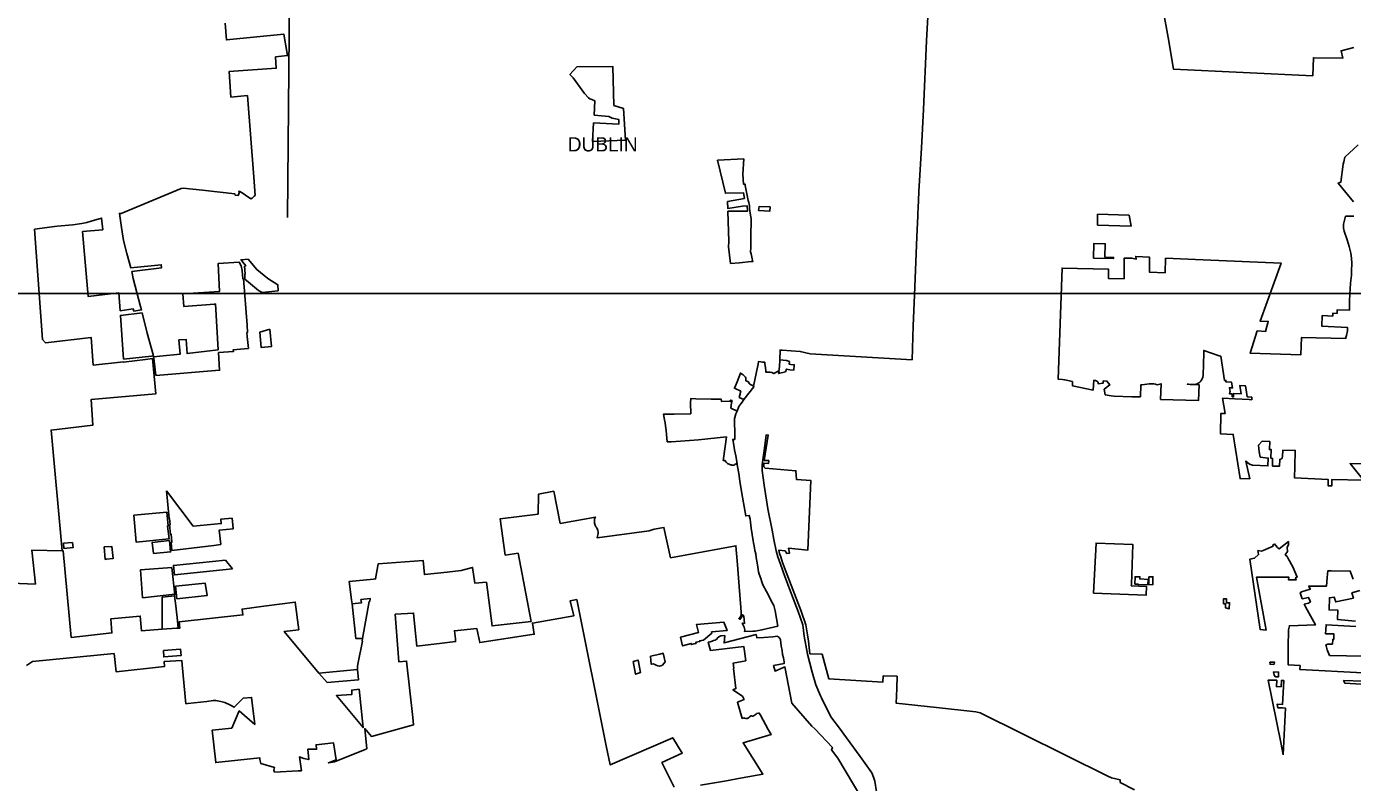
# Model space of a CAD drawing. Extents: x 1729596 to 1925846, y 659247 to 911751.
# Drawn here: x 1771869 to 1818365, y 748344 to 774852 of the extents above; entities that cross this region are included whole.
import ezdxf

# ---------------------------------------------------------------- set-up
doc = ezdxf.new("R2010")
doc.units = 0
for name, color, linetype in [('GM_X_Adjacent_County', 7, 'Continuous'), ('GM_X_Corporation', 7, 'Continuous'), ('GM_X_Corporation_Text', 7, 'Continuous'), ('SC_Scratch1', 7, 'Continuous')]:
    doc.layers.add(name, color=color, linetype=linetype)

msp = doc.modelspace()

# ---------------------------------------------------------------- linework, layer by layer
at = {"layer": 'GM_X_Adjacent_County'}
msp.add_line((1781136, 781321), (1781021, 768152), dxfattribs=at)
at = {"layer": 'GM_X_Corporation'}
for points in [[(1770221, 755380), (1772181, 755302), (1772057, 756492), (1773124, 756470), (1773153, 756469), (1773437, 753432), (1774866, 753591), (1774825, 754079), (1775856, 754180), (1775906, 753660), (1776624, 753722), (1777130, 753751), (1777182, 753756), (1777187, 753756), (1777192, 753756), (1777203, 753757), (1777227, 753759), (1777248, 753761), (1777222, 753980), (1779459, 754220), (1779429, 754427), (1780187, 754529), (1781295, 754669), (1781415, 753697), (1780909, 753642), (1782119, 752179), (1782408, 751849), (1783508, 751942), (1783479, 752309), (1783471, 752408), (1783484, 752497), (1783649, 753302), (1783633, 753301), (1783649, 753390), (1783882, 754688), (1783903, 754693), (1783921, 754795), (1783593, 754757), (1783615, 754639), (1783284, 754607), (1783265, 754751), (1783184, 755392), (1784040, 755478), (1784107, 755485), (1784200, 756011), (1785774, 756133), (1785821, 755634), (1786620, 755722), (1787106, 755772), (1787508, 755887), (1787585, 755334), (1787998, 755364), (1788193, 753835), (1789563, 753993), (1789108, 756382), (1788659, 756318), (1788479, 757590), (1789807, 757755), (1789818, 758450), (1790355, 758555), (1790586, 757428), (1791817, 757651), (1791798, 757614), (1791788, 757587), (1791780, 757546), (1791782, 757487), (1791788, 757438), (1791805, 757364), (1791835, 757312), (1791867, 757269), (1791892, 757218), (1791908, 757179), (1791915, 757135), (1791911, 757075), (1791904, 757024), (1791892, 756983), (1791876, 756928), (1793703, 757167), (1793873, 757222), (1794220, 757291), (1794455, 756226), (1796742, 756644), (1796798, 755979), (1796859, 755222), (1796915, 754482), (1796927, 754304), (1796931, 754250), (1796929, 754213), (1796912, 754181), (1796877, 754133), (1796843, 754097), (1796883, 754064), (1796952, 754150), (1796983, 754223), (1797022, 754175), (1797047, 753919), (1796968, 753934), (1797035, 753796), (1797053, 753693), (1797049, 753638), (1797341, 753647), (1797421, 753653), (1797474, 753661), (1797655, 753696), (1798210, 753829), (1798116, 754362), (1798071, 754553), (1798026, 754636), (1797814, 755043), (1797693, 755276), (1797657, 755384), (1797616, 755493), (1797564, 755654), (1797534, 755727), (1797500, 755975), (1797475, 756104), (1797452, 756237), (1797445, 756358), (1797413, 756483), (1797382, 756639), (1797361, 756753), (1797349, 756823), (1797285, 757257), (1797242, 757581), (1797210, 757710), (1797087, 757691), (1796955, 758481), (1796885, 758915), (1796847, 759179), (1796806, 759422), (1796792, 759498), (1796775, 759605), (1796742, 759796), (1796699, 760004), (1796671, 760173), (1796631, 760376), (1796701, 760373), (1796705, 760456), (1796703, 760557), (1796705, 760694), (1796699, 760891), (1796690, 761106), (1796705, 761148), (1796741, 761269), (1796792, 761362), (1796847, 761530), (1796917, 761623), (1796961, 761681), (1797003, 761733), (1797028, 761773), (1797374, 762223), (1797363, 762240), (1797453, 762684), (1797500, 762912), (1797522, 763017), (1797533, 763101), (1797623, 763091), (1797676, 763083), (1797721, 763081), (1797757, 763077), (1797761, 763030), (1797770, 762968), (1797782, 762885), (1797788, 762787), (1797797, 762730), (1797881, 762730), (1797948, 762730), (1798010, 762716), (1798071, 762682), (1798232, 762768), (1798251, 762763), (1798259, 762760), (1798240, 762681), (1798478, 762748), (1798523, 762842), (1798636, 762814), (1798776, 762808), (1798789, 762992), (1798672, 762998), (1798612, 763008), (1798618, 763105), (1798514, 763138), (1798285, 763163), (1798291, 763505), (1798362, 763501), (1799001, 763458), (1799354, 763375), (1802922, 763165), (1802964, 764353), (1803002, 765433), (1803091, 767476), (1803123, 768218), (1803140, 768585), (1803149, 768674), (1803153, 768757), (1803163, 769065), (1803249, 770602), (1803319, 771942), (1803430, 774349), (1803483, 775420)], [(1803483, 775420), (1803430, 774349), (1803319, 771942), (1803249, 770602), (1803163, 769065), (1803153, 768757), (1803149, 768674), (1803140, 768585), (1803123, 768218), (1803091, 767476), (1803002, 765433), (1802964, 764353), (1802922, 763165), (1799354, 763375), (1799001, 763458), (1798362, 763501), (1798291, 763505), (1798285, 763163), (1798285, 763121), (1798261, 762817), (1798251, 762763), (1798232, 762768), (1798071, 762682), (1798010, 762716), (1797948, 762730), (1797881, 762730), (1797797, 762730), (1797788, 762787), (1797782, 762885), (1797770, 762968), (1797761, 763030), (1797757, 763077), (1797721, 763081), (1797676, 763083), (1797623, 763091), (1797533, 763101), (1797522, 763017), (1797500, 762912), (1797453, 762684), (1797363, 762240), (1797328, 762261), (1797285, 762286), (1797235, 762306), (1797215, 762337), (1797189, 762393), (1797166, 762407), (1797095, 762431), (1797095, 762464), (1797096, 762492), (1797098, 762526), (1797079, 762553), (1797035, 762603), (1796999, 762638), (1796960, 762661), (1796901, 762700), (1796787, 762397), (1796734, 762256), (1796695, 762167), (1796714, 762158), (1796917, 762062), (1796864, 761847), (1797028, 761773), (1797003, 761733), (1796961, 761681), (1796917, 761623), (1796847, 761530), (1796792, 761362), (1796570, 761475), (1796586, 761667), (1796609, 761738), (1796566, 761754), (1796559, 761715), (1796509, 761719), (1796236, 761708), (1796228, 761782), (1795879, 761782), (1795343, 761802), (1795167, 761813), (1795148, 761662), (1795159, 761273), (1794583, 761261), (1794207, 761261), (1794244, 761065), (1794262, 760959), (1794275, 760853), (1794298, 760683), (1794310, 760545), (1794319, 760417), (1794336, 760293), (1794473, 760293), (1794798, 760307), (1795429, 760358), (1796412, 760460), (1796307, 759710), (1796302, 759633), (1796357, 759638), (1796408, 759574), (1796455, 759524), (1796534, 759493), (1796552, 759487), (1796578, 759477), (1796599, 759476), (1796640, 759471), (1796685, 759467), (1796706, 759495), (1796737, 759516), (1796763, 759510), (1796792, 759498), (1796806, 759422), (1796847, 759179), (1796885, 758915), (1796955, 758481), (1797087, 757691), (1797210, 757710), (1797242, 757581), (1797285, 757257), (1797349, 756823), (1797361, 756753), (1797382, 756639), (1797413, 756483), (1797445, 756358), (1797452, 756237), (1797475, 756104), (1797500, 755975), (1797534, 755727), (1797564, 755654), (1797616, 755493), (1797657, 755384), (1797693, 755276), (1797814, 755043), (1798026, 754636), (1798071, 754553), (1798116, 754362), (1798210, 753829), (1797655, 753696), (1797474, 753661), (1797421, 753653), (1797341, 753647), (1797049, 753638), (1797053, 753693), (1797035, 753796), (1796968, 753934), (1797047, 753919), (1797022, 754175), (1796983, 754223), (1796952, 754150), (1796883, 754064), (1796843, 754097), (1796877, 754133), (1796912, 754181), (1796929, 754213), (1796931, 754250), (1796927, 754304), (1796915, 754482), (1796859, 755222), (1796798, 755979), (1796742, 756644), (1794455, 756226), (1794220, 757291), (1793873, 757222), (1793703, 757167), (1791876, 756928), (1791892, 756983), (1791904, 757024), (1791911, 757075), (1791915, 757135), (1791908, 757179), (1791892, 757218), (1791867, 757269), (1791835, 757312), (1791805, 757364), (1791788, 757438), (1791782, 757487), (1791780, 757546), (1791788, 757587), (1791798, 757614), (1791817, 757651), (1790586, 757428), (1790355, 758555), (1789818, 758450), (1789807, 757755), (1788479, 757590), (1788659, 756318), (1789108, 756382), (1789563, 753993), (1788193, 753835), (1787998, 755364), (1787585, 755334), (1787508, 755887), (1787106, 755772), (1786620, 755722), (1785821, 755634), (1785774, 756133), (1784200, 756011), (1784107, 755485), (1784040, 755478), (1783184, 755392), (1783265, 754751), (1783284, 754607), (1783421, 753391), (1783649, 753390), (1783633, 753301), (1783649, 753302), (1783484, 752497), (1783471, 752408), (1783479, 752309), (1782119, 752179), (1780909, 753642), (1781415, 753697), (1781295, 754669), (1780187, 754529), (1779429, 754427), (1779459, 754220), (1777222, 753980), (1777248, 753761), (1777227, 753759), (1777203, 753757), (1777192, 753756), (1777150, 754125), (1777091, 754630), (1777072, 754794), (1777061, 754886), (1776626, 754848), (1776624, 753722), (1775906, 753660), (1775856, 754180), (1774825, 754079), (1774866, 753591), (1773437, 753432), (1773153, 756469), (1773124, 756470), (1772730, 760702), (1774189, 760869), (1774141, 761779), (1776402, 761968), (1776281, 763207), (1776046, 763174), (1775267, 763080), (1775267, 763099), (1774207, 762980), (1774134, 763952), (1772529, 763765), (1772435, 763880), (1772154, 767744), (1772941, 767852), (1773496, 767895), (1773812, 767946), (1773981, 767984), (1774140, 768026), (1774502, 768137), (1774541, 767725), (1773835, 767662), (1774031, 765380), (1775103, 765517), (1775155, 764887), (1775613, 764948), (1775632, 764875), (1775901, 764913), (1775868, 765038), (1775612, 766018), (1775562, 766261), (1776602, 766385), (1776595, 766499), (1775530, 766385), (1775389, 766892), (1775267, 767351), (1775201, 767808), (1775125, 768301), (1775186, 768299), (1777296, 769167), (1777365, 769179), (1778041, 769112), (1779178, 768980), (1779186, 768933), (1779291, 768930), (1779312, 768982), (1779321, 769021), (1779329, 769061), (1779309, 769075), (1779349, 769065), (1779409, 769034), (1779471, 768997), (1779544, 768942), (1779731, 768815), (1779777, 768829), (1779819, 768873), (1779857, 768907), (1779885, 768930), (1779843, 769567), (1779616, 772429), (1779035, 772377), (1778973, 773273), (1780624, 773390), (1780602, 773789), (1781025, 773834), (1780894, 774583), (1778880, 774385), (1778835, 774970)], [(1811724, 775429), (1811904, 774466), (1812090, 773353), (1816972, 773128), (1816996, 773757), (1818030, 773743), (1817968, 774000), (1818411, 774114)], [(1818565, 770709), (1818102, 770270), (1818065, 770105), (1818040, 770031), (1817953, 769391), (1817862, 769359), (1818406, 768703)], [(1818407, 768198), (1818124, 768198), (1818056, 767922), (1818053, 767779), (1818074, 767676), (1818180, 767367), (1818251, 767133), (1818305, 766910), (1818332, 766734), (1818343, 766558), (1818335, 766269), (1818328, 766137), (1818297, 765848), (1818280, 765638), (1818270, 765475), (1818260, 765220), (1818258, 764901), (1817832, 764921), (1817826, 764791), (1817676, 764798), (1817672, 764698), (1817302, 764716), (1817285, 764346), (1818189, 764304), (1818189, 764182), (1818155, 764021), (1818138, 763950), (1818130, 763912), (1816580, 763951), (1816553, 763337), (1814774, 763400), (1815027, 764176), (1815311, 764158), (1815412, 764509), (1815124, 764526), (1815864, 766555), (1813131, 766674), (1811812, 766729), (1811796, 766216), (1811252, 766235), (1811245, 766768), (1810767, 766788), (1810783, 766695), (1810629, 766731), (1810459, 766734), (1810457, 766724), (1810356, 766725), (1810359, 766356), (1810358, 766008), (1809808, 766020), (1809808, 766345), (1808185, 766383), (1808045, 762485), (1808195, 762479), (1808275, 762459), (1808546, 762402), (1808548, 762250), (1809272, 762106), (1809298, 762449), (1809355, 762441), (1809405, 762419), (1809431, 762391), (1809443, 762364), (1809447, 762323), (1809626, 762351), (1809624, 762423), (1809754, 762422), (1809856, 762286), (1809663, 762131), (1809689, 761942), (1809909, 761903), (1810009, 761892), (1810629, 761862), (1810931, 761869), (1810942, 762284), (1810976, 762290), (1811074, 762298), (1811239, 762322), (1811286, 762320), (1811393, 762324), (1811462, 762312), (1811518, 762292), (1811655, 762328), (1811639, 761776), (1812969, 761741), (1812988, 762288), (1812831, 762297), (1812765, 762300), (1812678, 762305), (1812570, 762310), (1812577, 762312), (1812587, 762314), (1812598, 762314), (1812612, 762314), (1812803, 762305), (1812823, 762305), (1812879, 762313), (1812915, 762325), (1812956, 762343), (1812983, 762362), (1813016, 762387), (1813043, 762416), (1813064, 762442), (1813096, 762498), (1813105, 762523), (1813114, 762551), (1813132, 762620), (1813135, 762709), (1813138, 762923), (1813152, 763497), (1813695, 763309), (1813751, 763290), (1813882, 762443), (1813929, 762440), (1813930, 762390), (1814128, 762379), (1814159, 762182), (1814050, 762187), (1814072, 762041), (1814063, 762041), (1814063, 761994), (1814050, 761993), (1814049, 761973), (1814143, 761968), (1814141, 761868), (1814190, 761864), (1814194, 761986), (1814461, 761971), (1814414, 762262), (1814611, 762254), (1814648, 762026), (1814674, 761870), (1814703, 761869), (1814838, 761852), (1814834, 761764), (1814747, 761770), (1814240, 761799), (1813809, 761823), (1813899, 761281), (1813752, 761287), (1813737, 760570), (1814182, 760551), (1814422, 758999), (1814760, 758997), (1814628, 759613), (1814754, 759504), (1814855, 759472), (1815402, 759447), (1815409, 759720), (1815130, 759752), (1815096, 759938), (1815073, 760175), (1815200, 760311), (1815464, 760306), (1815454, 760019), (1815517, 760018), (1815505, 759712), (1815562, 759710), (1815562, 759440), (1815805, 759434), (1815815, 759675), (1815875, 759690), (1815905, 759726), (1815915, 759771), (1815924, 760001), (1816357, 759991), (1816345, 759421), (1816337, 759023), (1817510, 758970), (1817510, 758751), (1817645, 758748), (1817646, 758969), (1818746, 758949), (1818281, 759525), (1819580, 759501)], [(1810722, 748085), (1810221, 748346), (1810220, 748433), (1809917, 748503), (1809792, 748562), (1805306, 750790), (1805153, 750816), (1803782, 750969), (1802362, 751127), (1802386, 751643), (1802395, 752068), (1801904, 752081), (1801902, 751864), (1800004, 751976), (1799768, 752839), (1799337, 752860), (1799288, 753301), (1799259, 753517), (1799195, 753873), (1799030, 754356), (1798507, 755721), (1798384, 756061), (1798314, 756259), (1798276, 756372), (1798244, 756489), (1798467, 756467), (1798529, 756374), (1798628, 756388), (1798591, 756564), (1799270, 756493), (1799367, 758939), (1798870, 758963), (1798849, 759277), (1797769, 759368), (1797722, 759416), (1797725, 759540), (1797893, 759534), (1797896, 759634), (1797741, 759640), (1797877, 760524), (1797803, 760530), (1797766, 760246), (1797665, 759477), (1797660, 759284), (1797739, 758775), (1797865, 757935), (1798015, 757195), (1798077, 756860), (1798161, 756466), (1798219, 756258), (1798311, 755995), (1798463, 755566), (1798749, 754795), (1798922, 754336), (1799095, 753877), (1799143, 753477), (1799257, 752840), (1799415, 752215), (1799549, 751765), (1799716, 751380), (1799745, 751315), (1800064, 750675), (1800110, 750597), (1800378, 750247), (1800618, 749910), (1801104, 749259), (1801506, 748678), (1801573, 748527), (1801614, 748387), (1801674, 748018)], [(1818387, 755471), (1818287, 755757), (1817619, 755760), (1817496, 755760), (1817477, 755529), (1817450, 755227), (1816850, 755229), (1816831, 755229), (1816887, 755122), (1816576, 755028), (1816532, 754999), (1816603, 754785), (1816825, 754835), (1816889, 754676), (1816826, 754636), (1816676, 754593), (1816713, 754504), (1817066, 753869), (1816155, 753841), (1816127, 753702), (1816127, 753603), (1816106, 753178), (1816113, 752649), (1816105, 752471), (1816527, 752441), (1816522, 752302), (1818729, 752189)], [(1794574, 748180), (1794147, 749043), (1794865, 749373), (1794531, 749912), (1792336, 748961), (1792198, 749626), (1791164, 754755), (1790938, 754719), (1791056, 754185), (1789610, 753934), (1789671, 753539), (1787760, 753249), (1787654, 753742), (1786874, 753665), (1786906, 753382), (1786916, 753283), (1786443, 753233), (1785553, 753125), (1785499, 753683), (1785442, 754285), (1784796, 754242), (1784920, 752578), (1785195, 752599), (1785416, 750625), (1785444, 750360), (1783963, 749959), (1783729, 750233), (1783799, 749524), (1783741, 749503), (1782666, 749072), (1782456, 749036), (1782732, 749144), (1782633, 749738), (1782024, 749670), (1782040, 749512), (1781732, 749512), (1781763, 749148), (1781598, 749189), (1781445, 749241), (1781509, 748753), (1781398, 748749), (1780567, 748710), (1780546, 748779), (1780565, 748866), (1780090, 749006), (1780055, 749146), (1780051, 749207), (1778506, 749039), (1778382, 750183), (1779068, 750252), (1779327, 750854), (1779872, 750383), (1779761, 751324), (1779466, 751295), (1779153, 750981), (1778998, 751072), (1778827, 751143), (1778680, 751179), (1778562, 751205), (1778501, 751220), (1778415, 751215), (1778192, 751189), (1777521, 751114), (1777461, 751105), (1777328, 752466), (1777311, 752624), (1776693, 752582), (1776711, 752414), (1775007, 752225), (1774938, 752864), (1772077, 752586), (1771864, 752450)], [(1818476, 754004), (1817844, 754054), (1817854, 754386), (1817542, 754395), (1817554, 754820), (1817723, 754846), (1817778, 754678), (1818397, 754803), (1818346, 754994), (1818628, 755073)], [(1818746, 752769), (1817564, 752801), (1817474, 752999), (1817439, 753141), (1817431, 753175), (1817499, 753189), (1817664, 753196), (1817671, 753360), (1817709, 753359), (1817714, 753553), (1817425, 753561), (1817430, 753702), (1817441, 753877), (1818479, 753812)], [(1801161, 747779), (1800318, 749198), (1800097, 749485), (1800128, 749567), (1799507, 750229), (1799412, 750316), (1798706, 751120), (1798462, 752398), (1798117, 752249), (1798068, 752442), (1798442, 752517), (1798433, 752573), (1798413, 752720), (1798384, 752837), (1798362, 752976), (1798333, 753132), (1798318, 753240), (1798305, 753344), (1798285, 753395), (1798262, 753427), (1798227, 753454), (1798198, 753471), (1798041, 753453), (1797723, 753424), (1797479, 753412), (1797476, 753439), (1797450, 753537), (1796330, 753237), (1796353, 753497), (1796210, 753481), (1796143, 753449), (1796092, 753406), (1796093, 753377), (1796014, 753336), (1795954, 753326), (1795913, 753303), (1795847, 753280), (1795773, 753260), (1795848, 752973), (1797026, 753110), (1797087, 752615), (1796652, 752533), (1796671, 752350), (1796658, 752339), (1796746, 751636), (1796638, 751592), (1796977, 751366), (1797033, 751257), (1796799, 751155), (1796966, 750588), (1797025, 750609), (1797047, 750598), (1797092, 750589), (1797136, 750587), (1797160, 750598), (1797188, 750613), (1797217, 750636), (1797237, 750657), (1797253, 750666), (1797285, 750676), (1797298, 750681), (1797320, 750675), (1797341, 750673), (1797359, 750677), (1797381, 750690), (1797421, 750713), (1797454, 750740), (1797471, 750760), (1797531, 750772), (1797564, 750776), (1797603, 750700), (1797878, 750206), (1797975, 750025), (1796995, 749737), (1797690, 748639), (1796961, 748506), (1796340, 748394), (1795502, 748255)], [(1818718, 751891), (1818056, 751920), (1818066, 751898), (1818099, 751822), (1820190, 751695)]]:
    msp.add_lwpolyline(points, dxfattribs=at)
for points in [[(1791769, 771744), (1792292, 771693), (1792400, 771637), (1792636, 771596), (1792636, 771425), (1791754, 771473), (1791720, 770818), (1792869, 770863), (1792799, 771981), (1792464, 772084), (1792432, 773446), (1791163, 773438), (1790923, 773175), (1791037, 773050), (1791431, 772506), (1791571, 772357), (1791625, 772322), (1791688, 772291), (1791795, 772249)], [(1796099, 770163), (1796374, 769005), (1797006, 769026), (1797045, 768825), (1796452, 768712), (1796465, 768470), (1796979, 768555), (1797142, 768559), (1797150, 768374), (1796465, 768373), (1796499, 767312), (1796490, 767130), (1796555, 766544), (1796870, 766570), (1797279, 766609), (1797338, 766615), (1797312, 766701), (1797277, 766882), (1797259, 766955), (1797271, 767095), (1797270, 767147), (1797268, 767221), (1797269, 767275), (1797264, 767337), (1797264, 767536), (1797272, 767608), (1797272, 767726), (1797279, 767856), (1797281, 767972), (1797274, 768111), (1797235, 768372), (1797225, 768494), (1797217, 768565), (1797195, 768683), (1797178, 768750), (1797069, 769278), (1797065, 769330), (1797015, 769322), (1796989, 769674), (1797017, 770212)], [(1797541, 768401), (1797935, 768382), (1797940, 768524), (1797562, 768542)], [(1809425, 767881), (1810604, 767857), (1810529, 768232), (1809425, 768268)], [(1809289, 766732), (1809985, 766716), (1809987, 766758), (1809683, 766765), (1809694, 767235), (1809300, 767244)], [(1777350, 765480), (1777390, 765033), (1778456, 765121), (1778497, 765124), (1778588, 763518), (1777500, 763383), (1777464, 763881), (1777215, 763863), (1777251, 763358), (1776548, 763289), (1776325, 763267), (1776334, 763222), (1776405, 762617), (1778638, 762800), (1778601, 763421), (1779128, 763459), (1779121, 763518), (1779630, 763563), (1779650, 763567), (1779608, 763988), (1779595, 764118), (1779623, 764127), (1779603, 764375), (1779472, 766012), (1779452, 766010), (1779430, 766292), (1779392, 766458), (1779331, 766585), (1778592, 766543), (1778640, 765564)], [(1779526, 765996), (1779649, 765886), (1780007, 765600), (1780127, 765528), (1780688, 765588), (1780677, 765797), (1780336, 766018), (1779945, 766331), (1779640, 766689), (1779392, 766675), (1779449, 766592), (1779558, 766458), (1779517, 766446), (1779531, 766180), (1779519, 766152)], [(1775930, 764813), (1775164, 764721), (1775275, 763188), (1776254, 763296), (1776316, 763302), (1776105, 764098)], [(1780404, 764245), (1780055, 764138), (1780095, 763598), (1780455, 763628)], [(1776781, 758571), (1776874, 757598), (1776884, 757599), (1776909, 757379), (1776884, 757376), (1776915, 757049), (1776937, 757054), (1776962, 756765), (1776941, 756764), (1776966, 756480), (1778434, 756650), (1778682, 756690), (1778628, 757192), (1779114, 757236), (1779113, 757254), (1779078, 757609), (1778681, 757577), (1778697, 757425), (1777708, 757333)], [(1775632, 757715), (1775719, 756770), (1776867, 756883), (1776810, 757337), (1776839, 757343), (1776787, 757819)], [(1773167, 756733), (1773180, 756550), (1773499, 756580), (1773477, 756755)], [(1774587, 756604), (1774629, 756166), (1774663, 756170), (1774909, 756203), (1774860, 756623)], [(1776879, 756830), (1776278, 756765), (1776322, 756377), (1776922, 756430)], [(1810612, 755292), (1810658, 756694), (1809373, 756736), (1809288, 754986), (1811129, 754910), (1811144, 755214), (1810610, 755242)], [(1816229, 755985), (1816155, 756120), (1816137, 756153), (1816070, 756268), (1816006, 756329), (1816086, 756440), (1816075, 756589), (1816125, 756693), (1816118, 756793), (1815798, 756532), (1815732, 756586), (1815668, 756669), (1815627, 756709), (1815604, 756690), (1815562, 756650), (1815582, 756628), (1815234, 756477), (1815172, 756459), (1815052, 756473), (1815075, 756335), (1814933, 756204), (1814761, 756173), (1815125, 753710), (1815333, 753688), (1815005, 755547), (1816128, 755547), (1816123, 755447), (1816205, 755447), (1816386, 755447), (1816362, 755515), (1816424, 755540), (1816273, 755901)], [(1779096, 755830), (1778843, 756143), (1777018, 755954), (1777056, 755620)], [(1776970, 755885), (1775862, 755797), (1775938, 754823), (1777065, 754950), (1777068, 754919)], [(1777098, 755224), (1777144, 754785), (1778199, 754896), (1778137, 755331)], [(1810728, 755301), (1810857, 755297), (1810856, 755285), (1811191, 755275), (1811195, 755462), (1810908, 755482), (1810911, 755558), (1810741, 755559)], [(1811226, 755561), (1811222, 755283), (1811362, 755280), (1811366, 755559)], [(1813846, 754609), (1813914, 754608), (1813912, 754471), (1814045, 754434), (1814053, 754644), (1813942, 754646), (1813944, 754786), (1813847, 754788)], [(1794796, 753442), (1794876, 753131), (1795181, 753219), (1795192, 753180), (1795272, 753203), (1795346, 753220), (1795335, 753259), (1795480, 753291), (1795474, 753312), (1795544, 753328), (1795606, 753339), (1795899, 753577), (1795891, 753624), (1796434, 753669), (1796318, 753969), (1795366, 753888), (1795438, 753609)], [(1776671, 752975), (1776681, 752746), (1777291, 752794), (1777271, 753017)], [(1793745, 752771), (1793775, 752489), (1793787, 752492), (1793842, 752499), (1793897, 752486), (1793951, 752453), (1794009, 752431), (1794065, 752420), (1794115, 752433), (1794167, 752458), (1794222, 752514), (1794260, 752570), (1794199, 752878), (1794082, 752848)], [(1793137, 752583), (1793226, 752140), (1793393, 752195), (1793317, 752638)], [(1815466, 752566), (1815477, 752498), (1815478, 752490), (1815609, 752484), (1815614, 752498), (1815636, 752559)], [(1815938, 749313), (1816016, 750955), (1815906, 750958), (1815742, 750964), (1815723, 751085), (1815913, 751081), (1815947, 751700), (1815959, 751917), (1815874, 751921), (1815861, 751703), (1815700, 751709), (1815710, 751929), (1815407, 751926), (1815849, 749748)], [(1815597, 752221), (1815616, 752105), (1815664, 752051), (1815768, 752046), (1815776, 752213)], [(1783531, 751616), (1783273, 751584), (1783278, 751434), (1782734, 751391), (1783671, 750271)]]:
    msp.add_lwpolyline(points, close=True, dxfattribs=at)
at = {"layer": 'SC_Scratch1'}
msp.add_lwpolyline([(1729596, 899996), (1925846, 899996), (1925846, 765496), (1729596, 765496)], close=True, dxfattribs=at)

# ---------------------------------------------------------------- texts
at = {"layer": 'GM_X_Corporation_Text'}
msp.add_text('DUBLIN', height=500, rotation=0, dxfattribs=at).set_placement((1790848, 770472))

doc.saveas('drawing.dxf')
